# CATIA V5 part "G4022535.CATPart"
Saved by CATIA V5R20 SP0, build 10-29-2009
Part number: G4022535
Revision: 4
Definition: design
Nomenclature: G4022535
Source: made
Description: NOT SPECIFIED
Bounding box of the stored display mesh (mm): x -18 to 35, y -17.817 to 17.817, z -18 to 18
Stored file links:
  C:\Users\Raffaele\Desktop\3D X SITO CF\BOLEX\26-BUSH REF 402\G4022535.CATPart
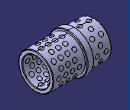
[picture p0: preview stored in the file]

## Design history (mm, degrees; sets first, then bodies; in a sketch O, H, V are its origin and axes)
Body1 "MANIFOLD_SOLID_BREP #11647" (main body)
  Solid1: solid without history
Body2 "MANIFOLD_SOLID_BREP #11798"
  Solid2: solid without history
Body3 "MANIFOLD_SOLID_BREP #11949"
  Solid3: solid without history
Body4 "MANIFOLD_SOLID_BREP #12100"
  Solid4: solid without history
Body5 "MANIFOLD_SOLID_BREP #12251"
  Solid5: solid without history
Body6 "MANIFOLD_SOLID_BREP #12400"
  Solid6: solid without history
Body7 "MANIFOLD_SOLID_BREP #12549"
  Solid7: solid without history
Body8 "MANIFOLD_SOLID_BREP #12698"
  Solid8: solid without history
Body9 "MANIFOLD_SOLID_BREP #12847"
  Solid9: solid without history
Body10 "MANIFOLD_SOLID_BREP #12996"
  Solid10: solid without history
Body11 "MANIFOLD_SOLID_BREP #13145"
  Solid11: solid without history
Body12 "MANIFOLD_SOLID_BREP #13294"
  Solid12: solid without history
Body13 "MANIFOLD_SOLID_BREP #13443"
  Solid13: solid without history
Body14 "MANIFOLD_SOLID_BREP #13592"
  Solid14: solid without history
Body15 "MANIFOLD_SOLID_BREP #13741"
  Solid15: solid without history
Body16 "MANIFOLD_SOLID_BREP #13890"
  Solid16: solid without history
Body17 "MANIFOLD_SOLID_BREP #14039"
  Solid17: solid without history
Body18 "MANIFOLD_SOLID_BREP #14188"
  Solid18: solid without history
Body19 "MANIFOLD_SOLID_BREP #14337"
  Solid19: solid without history
Body20 "MANIFOLD_SOLID_BREP #14486"
  Solid20: solid without history
Body21 "MANIFOLD_SOLID_BREP #14635"
  Solid21: solid without history
Body22 "MANIFOLD_SOLID_BREP #14784"
  Solid22: solid without history
Body23 "MANIFOLD_SOLID_BREP #14933"
  Solid23: solid without history
Body24 "MANIFOLD_SOLID_BREP #15082"
  Solid24: solid without history
Body25 "MANIFOLD_SOLID_BREP #15231"
  Solid25: solid without history
Body26 "MANIFOLD_SOLID_BREP #15380"
  Solid26: solid without history
Body27 "MANIFOLD_SOLID_BREP #15529"
  Solid27: solid without history
Body28 "MANIFOLD_SOLID_BREP #15678"
  Solid28: solid without history
Body29 "MANIFOLD_SOLID_BREP #15827"
  Solid29: solid without history
Body30 "MANIFOLD_SOLID_BREP #15976"
  Solid30: solid without history
Body31 "MANIFOLD_SOLID_BREP #16125"
  Solid31: solid without history
Body32 "MANIFOLD_SOLID_BREP #16276"
  Solid32: solid without history
Body33 "MANIFOLD_SOLID_BREP #16427"
  Solid33: solid without history
Body34 "MANIFOLD_SOLID_BREP #16576"
  Solid34: solid without history
Body35 "MANIFOLD_SOLID_BREP #16725"
  Solid35: solid without history
Body36 "MANIFOLD_SOLID_BREP #16874"
  Solid36: solid without history
Body37 "MANIFOLD_SOLID_BREP #17023"
  Solid37: solid without history
Body38 "MANIFOLD_SOLID_BREP #17172"
  Solid38: solid without history
Body39 "MANIFOLD_SOLID_BREP #17321"
  Solid39: solid without history
Body40 "MANIFOLD_SOLID_BREP #17470"
  Solid40: solid without history
Body41 "MANIFOLD_SOLID_BREP #17619"
  Solid41: solid without history
Body42 "MANIFOLD_SOLID_BREP #17768"
  Solid42: solid without history
Body43 "MANIFOLD_SOLID_BREP #17917"
  Solid43: solid without history
Body44 "MANIFOLD_SOLID_BREP #18066"
  Solid44: solid without history
Body45 "MANIFOLD_SOLID_BREP #18215"
  Solid45: solid without history
Body46 "MANIFOLD_SOLID_BREP #18364"
  Solid46: solid without history
Body47 "MANIFOLD_SOLID_BREP #18513"
  Solid47: solid without history
Body48 "MANIFOLD_SOLID_BREP #18662"
  Solid48: solid without history
Body49 "MANIFOLD_SOLID_BREP #18811"
  Solid49: solid without history
Body50 "MANIFOLD_SOLID_BREP #18960"
  Solid50: solid without history
Body51 "MANIFOLD_SOLID_BREP #19109"
  Solid51: solid without history
Body52 "MANIFOLD_SOLID_BREP #19258"
  Solid52: solid without history
Body53 "MANIFOLD_SOLID_BREP #19407"
  Solid53: solid without history
Body54 "MANIFOLD_SOLID_BREP #19558"
  Solid54: solid without history
Body55 "MANIFOLD_SOLID_BREP #19709"
  Solid55: solid without history
Body56 "MANIFOLD_SOLID_BREP #19860"
  Solid56: solid without history
Body57 "MANIFOLD_SOLID_BREP #20011"
  Solid57: solid without history
Body58 "MANIFOLD_SOLID_BREP #20160"
  Solid58: solid without history
Body59 "MANIFOLD_SOLID_BREP #20309"
  Solid59: solid without history
Body60 "MANIFOLD_SOLID_BREP #20458"
  Solid60: solid without history
Body61 "MANIFOLD_SOLID_BREP #20607"
  Solid61: solid without history
Body62 "MANIFOLD_SOLID_BREP #20756"
  Solid62: solid without history
Body63 "MANIFOLD_SOLID_BREP #20905"
  Solid63: solid without history
Body64 "MANIFOLD_SOLID_BREP #21054"
  Solid64: solid without history
Body65 "MANIFOLD_SOLID_BREP #21203"
  Solid65: solid without history
Body66 "MANIFOLD_SOLID_BREP #21352"
  Solid66: solid without history
Body67 "MANIFOLD_SOLID_BREP #21501"
  Solid67: solid without history
Body68 "MANIFOLD_SOLID_BREP #21650"
  Solid68: solid without history
Body69 "MANIFOLD_SOLID_BREP #21799"
  Solid69: solid without history
Body70 "MANIFOLD_SOLID_BREP #21948"
  Solid70: solid without history
Body71 "MANIFOLD_SOLID_BREP #22097"
  Solid71: solid without history
Body72 "MANIFOLD_SOLID_BREP #22248"
  Solid72: solid without history
Body73 "MANIFOLD_SOLID_BREP #22399"
  Solid73: solid without history
Body74 "MANIFOLD_SOLID_BREP #22548"
  Solid74: solid without history
Body75 "MANIFOLD_SOLID_BREP #22697"
  Solid75: solid without history
Body76 "MANIFOLD_SOLID_BREP #22846"
  Solid76: solid without history
Body77 "MANIFOLD_SOLID_BREP #22995"
  Solid77: solid without history
Body78 "MANIFOLD_SOLID_BREP #23144"
  Solid78: solid without history
Body79 "MANIFOLD_SOLID_BREP #23293"
  Solid79: solid without history
Body80 "MANIFOLD_SOLID_BREP #23442"
  Solid80: solid without history
Body81 "MANIFOLD_SOLID_BREP #23591"
  Solid81: solid without history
